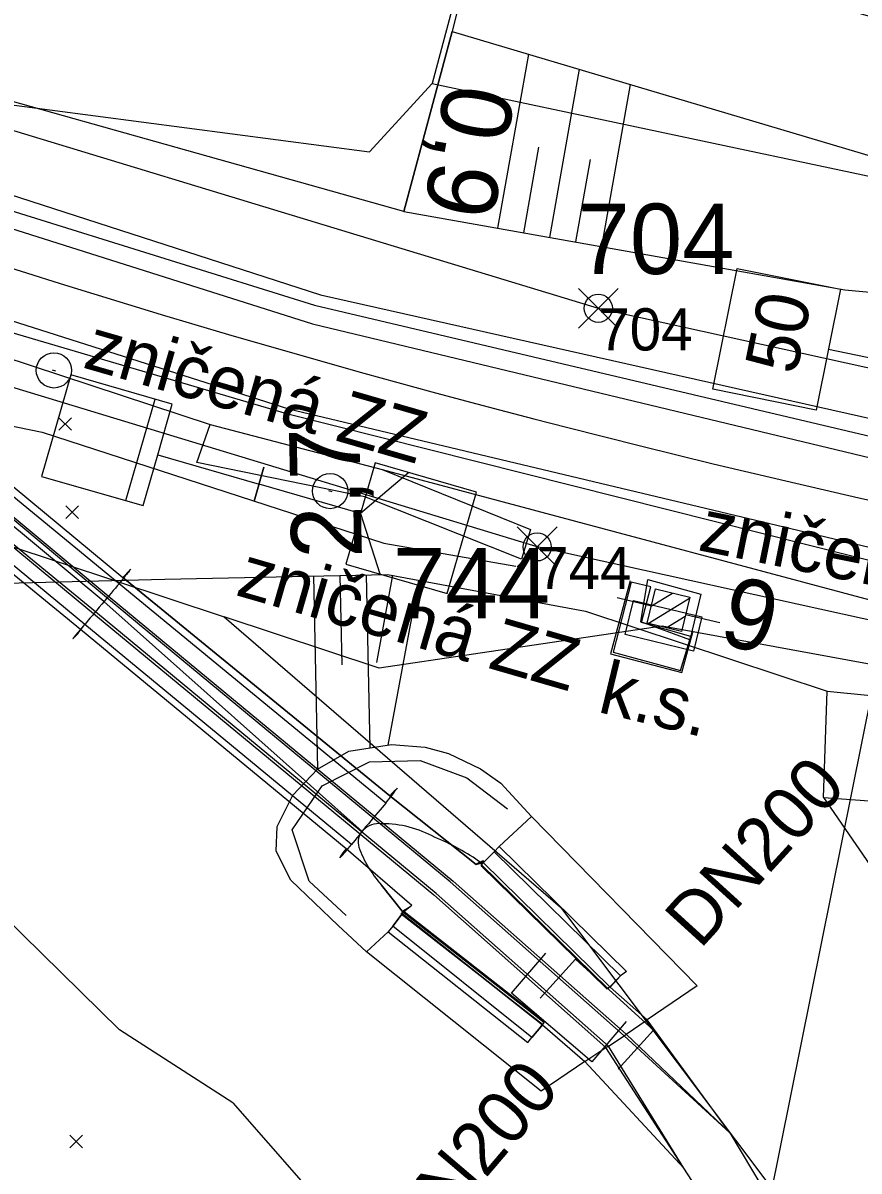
# Model space of a CAD drawing. Extents: x -800194 to -799078, y -1007177 to -1006597.
# Drawn here: x -799739 to -799715.24, y -1007007.87 to -1006975.25 of the extents above; entities that cross this region are included whole.
import ezdxf

# ---------------------------------------------------------------- set-up
doc = ezdxf.new("R2010")
doc.units = 0
for name, color, linetype in [('02_Osa_koleje', 7, 'Continuous'), ('Obvod stavby', 7, 'Continuous'), ('Vrstva 11', 7, 'Continuous'), ('Vrstva 12', 7, 'Continuous'), ('Vrstva 16', 7, 'Continuous'), ('Vrstva 17', 7, 'Continuous'), ('Vrstva 18', 7, 'Continuous'), ('Vrstva 23', 7, 'Continuous'), ('Vrstva 25', 7, 'Continuous'), ('Vrstva 4', 7, 'Continuous'), ('Vrstva 43', 7, 'Continuous'), ('Vrstva 48', 7, 'Continuous'), ('Vrstva 49', 7, 'Continuous'), ('Vrstva 5', 7, 'Continuous'), ('Vrstva 50', 7, 'Continuous'), ('Vrstva 55', 7, 'Continuous'), ('Vrstva 60', 7, 'Continuous'), ('Vrstva 7', 7, 'Continuous')]:
    doc.layers.add(name, color=color, linetype=linetype)

msp = doc.modelspace()

# ---------------------------------------------------------------- linework, layer by layer
at = {"layer": '02_Osa_koleje'}
msp.add_lwpolyline([(-799739.853, -1006982.055), (-799738.9, -1006982.357), (-799737.946, -1006982.656), (-799736.991, -1006982.951), (-799736.034, -1006983.244), (-799735.077, -1006983.533), (-799734.119, -1006983.819), (-799733.16, -1006984.102), (-799732.199, -1006984.381), (-799731.238, -1006984.657), (-799730.276, -1006984.93), (-799729.313, -1006985.2), (-799728.35, -1006985.467), (-799727.385, -1006985.73), (-799726.419, -1006985.989), (-799725.453, -1006986.246), (-799724.485, -1006986.499), (-799723.517, -1006986.749)], dxfattribs=at)
msp.add_arc((-799651.022, -1006703.891), 292, 255.62486, 308.20516, dxfattribs=at)
at = {"layer": 'Obvod stavby'}
for p, q in [((-799723.214, -1006983.924), (-799722.082, -1006982.793)), ((-799723.214, -1006982.793), (-799722.082, -1006983.924)), ((-799724.952, -1006990.705), (-799723.82, -1006989.574)), ((-799724.952, -1006989.574), (-799723.82, -1006990.705))]:
    msp.add_line(p, q, dxfattribs=at)
msp.add_lwpolyline([(-799664.426, -1006999.087), (-799684.601, -1006997.477), (-799704.619, -1006994.49), (-799724.386, -1006990.14), (-799749.554, -1006982.491), (-799772.102, -1006973.528), (-799780.707, -1006969.551), (-799777.674, -1006963.242), (-799769.263, -1006967.129), (-799747.228, -1006975.889), (-799722.648, -1006983.359), (-799703.35, -1006987.606), (-799683.806, -1006990.523), (-799664.228, -1006992.091)], dxfattribs=at)
for centre in [(-799722.648, -1006983.359), (-799724.386, -1006990.14)]:
    msp.add_circle(centre, 0.4, dxfattribs=at)
at = {"layer": 'Vrstva 11'}
for p, q in [((-799721.139, -1006991.823), (-799722.111, -1006991.588)), ((-799721.233, -1006992.314), (-799720.055, -1006991.593)), ((-799721.138, -1006991.816), (-799720.542, -1006991.451)), ((-799720.718, -1006992.438), (-799720.18, -1006992.109)), ((-799720.167, -1006992.057), (-799719.195, -1006992.29))]:
    msp.add_line(p, q, dxfattribs=at)
msp.add_lwpolyline([(-799721.022, -1006991.336), (-799720.05, -1006991.57), (-799720.284, -1006992.542), (-799721.256, -1006992.308)], close=True, dxfattribs=at)
at = {"layer": 'Vrstva 12'}
msp.add_lwpolyline([(-799721.236, -1006991.07), (-799719.737, -1006991.48), (-799720.049, -1006992.784), (-799721.435, -1006992.272), (-799721.236, -1006991.07)], dxfattribs=at)
at = {"layer": 'Vrstva 16'}
for p, q in [((-799725.462, -1006998.653), (-799724.55, -1006997.8)), ((-799728.219, -1007000.489), (-799728.813, -1006999.75)), ((-799721.913, -1007004.037), (-799726.857, -1006999.659)), ((-799727.258, -1006999.988), (-799722.361, -1007004.328)), ((-799727.952, -1007000.326), (-799728.231, -1007000.559)), ((-799728.231, -1007000.559), (-799724.23, -1007003.721)), ((-799728.622, -1007001.076), (-799729.241, -1007001.641)), ((-799721.857, -1007003.981), (-799721.255, -1007003.58)), ((-799723.028, -1007004.76), (-799722.434, -1007004.367))]:
    msp.add_line(p, q, dxfattribs=at)
for points in [[(-799726.857, -1006999.659), (-799736.574, -1006991.623), (-799742.439, -1006986.725), (-799754.518, -1006974.879), (-799763.734, -1006965.993), (-799777.293, -1006954.374), (-799779.945, -1006952.099), (-799783.722, -1006948.693)], [(-799783.708, -1006948.669), (-799779.9, -1006952.065), (-799777.252, -1006954.333), (-799763.672, -1006965.935), (-799754.476, -1006974.829), (-799742.393, -1006986.703), (-799736.524, -1006991.578), (-799726.778, -1006999.642)], [(-799784.356, -1006949.5), (-799780.347, -1006952.62), (-799777.716, -1006954.827), (-799764.168, -1006966.436), (-799754.935, -1006975.363), (-799742.857, -1006987.188), (-799736.94, -1006992.081), (-799727.324, -1007000.028)], [(-799727.258, -1006999.988), (-799736.887, -1006992.032), (-799742.859, -1006987.132), (-799754.894, -1006975.337), (-799764.135, -1006966.374), (-799777.698, -1006954.783), (-799780.331, -1006952.581), (-799784.321, -1006949.462)], [(-799779.465, -1006951.506), (-799778.251, -1006952.583), (-799776.738, -1006953.884), (-799763.224, -1006965.504), (-799753.999, -1006974.421), (-799741.964, -1006986.204), (-799736.168, -1006991.012), (-799728.577, -1006997.215), (-799726.123, -1006999.163)], [(-799727.952, -1007000.326), (-799729.82, -1006998.717), (-799737.37, -1006992.486), (-799743.358, -1006987.594), (-799755.401, -1006975.883), (-799764.592, -1006966.926), (-799778.073, -1006955.449), (-799779.598, -1006954.142), (-799780.843, -1006953.125)], [(-799724.268, -1007005.601), (-799729.241, -1007001.641), (-799730.043, -1007000.896), (-799731.391, -1006999.609), (-799731.807, -1006998.789), (-799731.776, -1006998.081), (-799731.332, -1006997.192), (-799730.628, -1006996.451), (-799729.736, -1006995.947), (-799728.528, -1006995.755), (-799727.566, -1006995.827), (-799726.904, -1006996.009), (-799726.001, -1006996.45), (-799725.419, -1006996.855), (-799724.55, -1006997.8), (-799719.837, -1007002.616)], [(-799719.837, -1007002.616), (-799721.255, -1007003.58), (-799722.309, -1007002.649), (-799722.019, -1007002.331), (-799725.605, -1006998.806), (-799725.462, -1006998.653), (-799721.848, -1007002.204), (-799722.019, -1007002.331)], [(-799726.123, -1006999.163), (-799725.923, -1006999.111), (-799725.92, -1006999.107), (-799725.969, -1006999.167)], [(-799725.605, -1006998.806), (-799725.969, -1006999.167), (-799725.978, -1006999.12)], [(-799727.324, -1007000.028), (-799722.434, -1007004.367), (-799722.361, -1007004.328), (-799721.913, -1007004.037), (-799721.857, -1007003.981), (-799726.778, -1006999.642)], [(-799724.23, -1007003.721), (-799724.534, -1007004.077), (-799728.488, -1007000.913), (-799728.199, -1007000.524)], [(-799728.231, -1007000.559), (-799728.25, -1007000.58), (-799728.201, -1007000.516), (-799728.199, -1007000.524), (-799728.219, -1007000.489)], [(-799728.488, -1007000.913), (-799728.622, -1007001.076), (-799724.647, -1007004.218), (-799724.534, -1007004.077)], [(-799724.23, -1007003.721), (-799723.028, -1007004.76), (-799724.268, -1007005.601)]]:
    msp.add_lwpolyline(points, dxfattribs=at)
for centre, major_axis, ratio, start_param, end_param in [((-799728.904, -1006998.513), (-0.566, -0.095), 0.888473, 4.396597, 6.415472), ((-799729.06, -1007000.766), (-2.796, -1.224), 0.88479, 3.718308, 4.259024), ((-799730.273, -1007003.369), (-6.212, -1.397), 0.847151, 3.77745, 4.035936), ((-799725.41, -1006997.773), (-4.211, 0.231), 0.818659, 0.330695, 0.676051), ((-799727.773, -1007000.273), (1.862, 1.216), 0.026669, 5.99696, 6.747447), ((-799726.195, -1006999.167), (-2.024, -1.323), 0.007629, 6.252324, 6.798297)]:
    msp.add_ellipse(centre, major_axis=major_axis, ratio=ratio, start_param=start_param, end_param=end_param, dxfattribs=at)
at = {"layer": 'Vrstva 17'}
for points in [[(-799726.806, -1006975.491), (-799728.174, -1006980.607), (-799746.39, -1006975.498), (-799745.242, -1006970.318), (-799744.263, -1006965.815), (-799756.721, -1006963.941)], [(-799695.807, -1006967.611), (-799698.37, -1006979.283), (-799711.621, -1006976.014), (-799725.913, -1006971.918), (-799726.806, -1006975.491)], [(-799746.564, -1006986.717), (-799745.074, -1006985.521), (-799738.458, -1006986.883), (-799728.745, -1006990.03), (-799724.988, -1006990.685)], [(-799721.747, -1006991.106), (-799722.3, -1006993.177), (-799720.272, -1006993.705), (-799719.96, -1006992.563)], [(-799729.82, -1007000.617), (-799730.868, -1006999.634), (-799731.355, -1006998.181), (-799730.498, -1006996.925), (-799729.155, -1006996.246), (-799727.711, -1006996.213), (-799726.389, -1006996.698), (-799725.227, -1006997.578)]]:
    msp.add_lwpolyline(points, dxfattribs=at)
at = {"layer": 'Vrstva 18'}
for p, q in [((-799728.577, -1006997.215), (-799736.168, -1006991.012)), ((-799729.364, -1006998.225), (-799736.701, -1006991.694)), ((-799729.82, -1006998.717), (-799737.37, -1006992.486)), ((-799726.123, -1006999.163), (-799728.577, -1006997.215)), ((-799727.952, -1007000.326), (-799729.82, -1006998.717)), ((-799722.019, -1007002.331), (-799725.605, -1006998.806)), ((-799725.98, -1006999.167), (-799722.374, -1007002.692)), ((-799722.407, -1007002.695), (-799725.98, -1006999.2)), ((-799728.813, -1006999.75), (-799728.219, -1007000.489)), ((-799728.199, -1007000.524), (-799728.488, -1007000.913)), ((-799724.238, -1007003.715), (-799728.25, -1007000.58)), ((-799724.23, -1007003.721), (-799728.231, -1007000.559)), ((-799728.199, -1007000.524), (-799728.201, -1007000.516)), ((-799724.197, -1007003.62), (-799728.169, -1007000.506)), ((-799728.168, -1007000.512), (-799724.201, -1007003.621)), ((-799724.534, -1007004.077), (-799728.488, -1007000.913)), ((-799722.374, -1007002.692), (-799722.372, -1007002.691))]:
    msp.add_line(p, q, dxfattribs=at)
for points in [[(-799776.738, -1006953.884), (-799763.224, -1006965.504), (-799753.999, -1006974.421), (-799741.964, -1006986.204), (-799736.168, -1006991.012)], [(-799728.689, -1006997.417), (-799736.272, -1006991.186), (-799742.111, -1006986.385), (-799754.178, -1006974.631), (-799763.368, -1006965.72), (-799777.061, -1006954.31)], [(-799736.701, -1006991.694), (-799742.573, -1006986.82), (-799754.68, -1006975.182), (-799763.887, -1006966.256), (-799777.391, -1006954.732)], [(-799729.664, -1006998.596), (-799737.245, -1006992.341), (-799743.186, -1006987.438), (-799755.222, -1006975.72), (-799764.444, -1006966.802), (-799777.959, -1006955.323)], [(-799737.37, -1006992.486), (-799743.358, -1006987.594), (-799755.401, -1006975.883), (-799764.592, -1006966.926), (-799778.073, -1006955.449)], [(-799725.98, -1006999.167), (-799725.92, -1006999.107), (-799725.923, -1006999.111), (-799722.309, -1007002.649)], [(-799725.605, -1006998.806), (-799725.969, -1006999.167), (-799725.968, -1006999.201), (-799722.404, -1007002.693)], [(-799725.969, -1006999.167), (-799725.98, -1006999.167), (-799725.98, -1006999.2), (-799725.968, -1006999.201)], [(-799728.201, -1007000.516), (-799728.25, -1007000.58), (-799728.231, -1007000.559)], [(-799724.194, -1007003.649), (-799728.201, -1007000.516), (-799728.169, -1007000.506)], [(-799728.169, -1007000.506), (-799728.168, -1007000.512), (-799728.199, -1007000.524)], [(-799722.309, -1007002.649), (-799722.321, -1007002.641), (-799722.374, -1007002.692), (-799722.407, -1007002.695), (-799722.404, -1007002.693), (-799722.372, -1007002.691), (-799722.019, -1007002.331), (-799722.309, -1007002.649)], [(-799724.201, -1007003.621), (-799724.197, -1007003.656), (-799724.534, -1007004.077), (-799724.23, -1007003.721)], [(-799724.194, -1007003.649), (-799724.238, -1007003.715), (-799724.23, -1007003.721)], [(-799724.197, -1007003.656), (-799724.194, -1007003.649), (-799724.197, -1007003.62), (-799724.201, -1007003.621)]]:
    msp.add_lwpolyline(points, dxfattribs=at)
for centre, major_axis, ratio, start_param, end_param in [((-799736.897, -1006992.163), (-0.963, -1.369), 0.041864, 3.408659, 3.947328), ((-799737.23, -1006992.158), (1.296, 1.385), 0.007101, 5.99726, 6.885866), ((-799736.745, -1006991.75), (0.647, 0.768), 0.002373, 0.747313, 2.45121), ((-799736.371, -1006991.391), (-1.212, -1.352), 0.012722, 5.667277, 6.576621), ((-799736.715, -1006991.366), (0.854, 1.349), 0.064947, 3.376238, 3.945747), ((-799729.601, -1006998.375), (1.227, 1.391), 0.038982, 5.50568, 5.9942), ((-799729.675, -1006998.422), (1.311, 1.425), 0.009263, 6.006131, 6.851805), ((-799729.164, -1006998.01), (-0.65, -0.786), 0.017237, 3.872792, 5.567675), ((-799728.904, -1006998.513), (-0.566, -0.095), 0.888473, 4.396597, 6.415472), ((-799729.06, -1007000.766), (2.796, 1.224), 0.88479, 0.576715, 1.117431), ((-799730.273, -1007003.369), (-6.212, -1.397), 0.847151, 3.77745, 4.035936), ((-799728.754, -1006997.452), (-1.245, -1.521), 0.021997, 5.712311, 6.543003), ((-799728.95, -1006997.634), (-1.036, -1.326), 0.024932, 0.238319, 0.779035), ((-799725.41, -1006997.773), (-4.211, 0.231), 0.818659, 0.330695, 0.676051), ((-799727.773, -1007000.273), (1.862, 1.216), 0.026669, 5.99696, 6.747447), ((-799726.195, -1006999.167), (-2.024, -1.323), 0.007629, 6.252324, 6.798297)]:
    msp.add_ellipse(centre, major_axis=major_axis, ratio=ratio, start_param=start_param, end_param=end_param, dxfattribs=at)
at = {"layer": 'Vrstva 23'}
msp.add_lwpolyline([(-799721.159, -1006991.27), (-799721.712, -1006991.14), (-799722.223, -1006993.135), (-799720.312, -1006993.651), (-799720.015, -1006992.683), (-799721.422, -1006992.285), (-799721.159, -1006991.27)], dxfattribs=at)
at = {"layer": 'Vrstva 25'}
msp.add_lwpolyline([(-799721.886, -1006992.632), (-799721.652, -1006991.66), (-799719.708, -1006992.128), (-799719.942, -1006993.1), (-799721.886, -1006992.632)], dxfattribs=at)
at = {"layer": 'Vrstva 4'}
for points in [[(-799766.319, -1006970.565), (-799760.949, -1006972.542), (-799747.638, -1006977.46), (-799730.549, -1006982.982), (-799710.066, -1006987.578), (-799704.728, -1006988.346), (-799693.001, -1006990.373), (-799682.434, -1006991.64), (-799671.27, -1006992.619), (-799659.31, -1006993.026), (-799648.69, -1006993.125), (-799637.398, -1006992.704), (-799625.913, -1006992.175), (-799614.965, -1006990.831), (-799603.911, -1006989.312), (-799592.728, -1006987.172), (-799581.605, -1006984.547), (-799570.583, -1006981.598), (-799559.909, -1006978.216), (-799542.956, -1006972.25), (-799531.79, -1006967.658), (-799521.285, -1006962.191), (-799511.236, -1006957.129)], [(-799779.678, -1006964.304), (-799766.319, -1006970.565), (-799761.253, -1006973.176), (-799747.77, -1006978.421), (-799730.774, -1006983.8), (-799710.333, -1006988.709), (-799704.916, -1006989.741), (-799693.131, -1006991.407), (-799682.585, -1006992.929), (-799671.325, -1006993.879), (-799659.363, -1006994.45), (-799648.66, -1006994.501), (-799637.23, -1006994.127), (-799626.066, -1006993.335), (-799614.788, -1006992.17), (-799603.669, -1006990.506), (-799592.467, -1006988.452), (-799581.281, -1006985.916), (-799570.22, -1006982.998), (-799559.296, -1006979.606), (-799542.375, -1006973.485), (-799531.236, -1006968.774), (-799520.48, -1006963.762), (-799510.394, -1006958.536)], [(-799776.864, -1006969.085), (-799770.965, -1006971.646), (-799761.91, -1006975.649), (-799748.544, -1006980.777), (-799731.457, -1006986.215), (-799711.132, -1006991.054), (-799705.482, -1006992.16), (-799693.53, -1006994.084), (-799682.801, -1006995.384), (-799671.514, -1006996.319), (-799659.449, -1006996.851), (-799648.588, -1006996.949), (-799637.262, -1006996.573), (-799625.835, -1006995.773), (-799614.546, -1006994.586), (-799603.199, -1006992.945), (-799591.969, -1006990.857), (-799580.647, -1006988.335), (-799569.534, -1006985.311), (-799558.557, -1006981.947), (-799541.405, -1006975.739), (-799530.263, -1006971.071), (-799519.455, -1006966), (-799509.248, -1006960.724)], [(-799776.864, -1006969.085), (-799771.262, -1006971.982), (-799762.131, -1006976.093), (-799748.706, -1006981.286), (-799731.51, -1006986.353), (-799711.222, -1006991.459), (-799705.527, -1006992.587), (-799693.582, -1006994.543), (-799682.85, -1006995.904), (-799671.5, -1006996.805), (-799659.556, -1006997.356), (-799648.616, -1006997.341), (-799637.276, -1006997.071), (-799625.828, -1006996.297), (-799614.43, -1006995.109), (-799603.18, -1006993.475), (-799591.849, -1006991.264), (-799580.564, -1006988.698), (-799569.449, -1006985.746), (-799558.385, -1006982.386), (-799541.268, -1006976.227), (-799530.102, -1006971.505), (-799519.398, -1006966.36), (-799509.087, -1006961.127)], [(-799779.011, -1006963.023), (-799770.632, -1006967.944), (-799766.319, -1006970.565), (-799761.021, -1006972.82), (-799747.748, -1006977.966), (-799730.719, -1006983.271), (-799710.195, -1006988.108), (-799704.765, -1006989.181), (-799693.072, -1006990.965), (-799682.554, -1006992.238), (-799671.266, -1006993.222), (-799659.388, -1006993.765), (-799648.658, -1006993.824), (-799637.385, -1006993.531), (-799625.769, -1006992.728), (-799614.9, -1006991.542), (-799603.91, -1006989.963), (-799592.572, -1006987.892), (-799581.421, -1006985.419), (-799570.327, -1006982.332), (-799559.429, -1006979.066), (-799542.601, -1006973.013), (-799531.454, -1006968.25), (-799520.744, -1006963.214)], [(-799776.864, -1006969.085), (-799771.693, -1006972.522), (-799762.217, -1006976.394), (-799748.898, -1006981.647), (-799733.68, -1006986.66), (-799728.795, -1006987.945), (-799711.349, -1006992.599), (-799705.744, -1006994.116), (-799693.689, -1006996.09), (-799689.347, -1006996.226), (-799688.222, -1006996.296), (-799683.105, -1006997.407), (-799671.667, -1006998.275)], [(-799734.064, -1006987.737), (-799733.68, -1006986.66), (-799728.795, -1006987.945), (-799724.58, -1006989.646), (-799724.833, -1006990.487), (-799729.281, -1006988.715), (-799734.064, -1006987.737)]]:
    msp.add_lwpolyline(points, dxfattribs=at)
at = {"layer": 'Vrstva 43'}
for points in [[(-799721.858, -1007003.626), (-799722.831, -1007004.768), (-799725.115, -1007002.822), (-799724.142, -1007001.68)], [(-799724.303, -1007002.961), (-799723.293, -1007001.851), (-799721.075, -1007003.871), (-799722.084, -1007004.98)]]:
    msp.add_lwpolyline(points, dxfattribs=at)
at = {"layer": 'Vrstva 48'}
for p, q in [((-799725.506, -1006981.082), (-799724.627, -1006976.139)), ((-799724.029, -1006981.344), (-799723.18, -1006976.569)), ((-799722.552, -1006981.607), (-799721.733, -1006977)), ((-799724.767, -1006981.213), (-799724.335, -1006978.784)), ((-799723.291, -1006981.476), (-799722.873, -1006979.13)), ((-799729.993, -1006990.948), (-799729.94, -1006993.49)), ((-799729.243, -1006990.933), (-799729.14, -1006995.852)), ((-799728.495, -1006990.947), (-799728.955, -1006993.422)), ((-799730.742, -1006990.964), (-799730.628, -1006996.451)), ((-799727.758, -1006991.084), (-799728.628, -1006995.771))]:
    msp.add_line(p, q, dxfattribs=at)
at = {"layer": 'Vrstva 49'}
for p, q in [((-799737.98, -1006986.471), (-799737.626, -1006986.825)), ((-799737.98, -1006986.825), (-799737.626, -1006986.471)), ((-799737.782, -1006988.977), (-799737.428, -1006989.331)), ((-799737.782, -1006989.331), (-799737.428, -1006988.977)), ((-799716.248, -1006997.261), (-799716.141, -1006994.243)), ((-799718.907, -1007006.786), (-799721.255, -1007003.58)), ((-799718.907, -1007006.786), (-799721.857, -1007003.981)), ((-799722.361, -1007004.328), (-799722.434, -1007004.367)), ((-799720.214, -1007007.792), (-799722.361, -1007004.328)), ((-799720.214, -1007007.792), (-799722.434, -1007004.367)), ((-799720.214, -1007007.792), (-799723.028, -1007004.76)), ((-799737.668, -1007006.857), (-799737.314, -1007007.211)), ((-799737.668, -1007007.211), (-799737.314, -1007006.857))]:
    msp.add_line(p, q, dxfattribs=at)
for points in [[(-799728.174, -1006980.607), (-799726.806, -1006975.491), (-799714.47, -1006979.159), (-799704.928, -1006981.248), (-799699.097, -1006983.466), (-799688.779, -1006985.763), (-799678.423, -1006987.219), (-799669.363, -1006989.921)], [(-799728.174, -1006980.607), (-799715.637, -1006982.837), (-799705.851, -1006983.743), (-799700.586, -1006985.508), (-799691.67, -1006987.253), (-799678.693, -1006988.601), (-799669.363, -1006989.921)], [(-799733.039, -1007005.939), (-799736.26, -1007003.86), (-799742.34, -1006997.896), (-799743.342, -1006994.901), (-799739.871, -1006991.182), (-799734.968, -1006991.052), (-799728.642, -1006990.92), (-799723.01, -1006991.966), (-799716.141, -1006994.243), (-799710.319, -1006994.817)], [(-799723.028, -1007004.76), (-799724.268, -1007005.601), (-799729.241, -1007001.641), (-799730.043, -1007000.896), (-799731.391, -1006999.609), (-799731.807, -1006998.789), (-799731.776, -1006998.081), (-799731.332, -1006997.192), (-799730.628, -1006996.451), (-799729.736, -1006995.947), (-799728.528, -1006995.755), (-799727.566, -1006995.827), (-799726.904, -1006996.009), (-799726.001, -1006996.45), (-799725.419, -1006996.855), (-799724.55, -1006997.8), (-799719.837, -1007002.616), (-799721.255, -1007003.58)], [(-799716.248, -1006997.261), (-799711.439, -1007004.242), (-799711.113, -1007006.25), (-799707.442, -1007011.019), (-799702.585, -1007019.595), (-799698.243, -1007027.001), (-799684.872, -1007037.347), (-799668.902, -1007051.666)], [(-799716.248, -1006997.261), (-799713.515, -1006997.457), (-799709.895, -1006999.809), (-799706.577, -1006999.538), (-799702.816, -1006999.606), (-799701.051, -1007000.939), (-799691.907, -1007002.76), (-799679.882, -1007005.3), (-799670.416, -1007005.115), (-799649.119, -1007006.099), (-799641.812, -1007006.94)], [(-799718.907, -1007006.786), (-799721.913, -1007004.037), (-799721.857, -1007003.981)], [(-799733.039, -1007005.939), (-799730.086, -1007009.294), (-799720.161, -1007021.94)], [(-799718.907, -1007006.786), (-799714.515, -1007014.16), (-799704.214, -1007027.237), (-799692.017, -1007040.081), (-799674.887, -1007054.948)], [(-799676.078, -1007055.763), (-799692.866, -1007041.408), (-799705.479, -1007027.95), (-799715.681, -1007014.777), (-799720.214, -1007007.792)]]:
    msp.add_lwpolyline(points, dxfattribs=at)
at = {"layer": 'Vrstva 5'}
for p, q in [((-799713.166, -1006985.129), (-799716.107, -1006984.535)), ((-799720.48, -1007022.094), (-799714.568, -1006992.803))]:
    msp.add_line(p, q, dxfattribs=at)
msp.add_lwpolyline([(-799715.76, -1006982.82), (-799716.453, -1006986.251), (-799719.394, -1006985.657), (-799718.701, -1006982.227)], close=True, dxfattribs=at)
at = {"layer": 'Vrstva 50'}
for p, q in [((-799738.172, -1006985.111), (-799738.076, -1006985.139)), ((-799730.319, -1006988.54), (-799730.223, -1006988.568))]:
    msp.add_line(p, q, dxfattribs=at)
for centre in [(-799738.124, -1006985.125), (-799730.271, -1006988.554)]:
    msp.add_circle(centre, 0.5, dxfattribs=at)
at = {"layer": 'Vrstva 55'}
msp.add_line((-799727.37, -1006976.97), (-799691.32, -1006984.61), dxfattribs=at)
for points in [[(-799785.23, -1006937.71), (-799791.69, -1006959.99), (-799791.97, -1006960.97), (-799746.76, -1006987.67), (-799745.68, -1006988.03), (-799733.28, -1006992.13)], [(-799741.57, -1006968.68), (-799738.19, -1006957.26), (-799723.4, -1006962.09), (-799727.37, -1006976.97)], [(-799741.57, -1006968.68), (-799744.25, -1006976.52), (-799740.85, -1006977.38), (-799729.15, -1006978.91), (-799727.37, -1006976.97)], [(-799667.22, -1007009.16), (-799678.94, -1007000.07), (-799720.83, -1006992.39), (-799728.88, -1006993.59), (-799733.28, -1006992.13)], [(-799733.28, -1006992.13), (-799723.72, -1007000.38), (-799700.54, -1007031.23)]]:
    msp.add_lwpolyline(points, dxfattribs=at)
at = {"layer": 'Vrstva 60'}
for p, q in [((-799722.648, -1006983.359), (-799722.648, -1006983.359)), ((-799724.386, -1006990.14), (-799724.386, -1006990.14))]:
    msp.add_line(p, q, dxfattribs=at)
at = {"layer": 'Vrstva 7'}
for p, q in [((-799736.08, -1006988.826), (-799735.248, -1006985.944)), ((-799735.174, -1006987.526), (-799732.292, -1006988.358)), ((-799732.153, -1006987.878), (-799732.431, -1006988.838)), ((-799732.431, -1006988.838), (-799732.153, -1006987.878)), ((-799729.41, -1006989.19), (-799732.292, -1006988.358))]:
    msp.add_line(p, q, dxfattribs=at)
for points in [[(-799735.174, -1006987.526), (-799734.758, -1006986.085), (-799737.641, -1006985.253), (-799738.473, -1006988.136), (-799735.59, -1006988.967), (-799735.174, -1006987.526)], [(-799729.41, -1006989.19), (-799729.826, -1006990.631), (-799726.943, -1006991.463), (-799726.111, -1006988.58), (-799728.994, -1006987.749), (-799729.41, -1006989.19)], [(-799728.031, -1006988.026), (-799729.41, -1006989.19), (-799728.863, -1006990.909)]]:
    msp.add_lwpolyline(points, dxfattribs=at)

# ---------------------------------------------------------------- texts
at = {"layer": 'Obvod stavby'}
for s, p in [('704', (-799723.238, -1006982.386)), ('744', (-799728.485, -1006992.174))]:
    msp.add_text(s, height=2, rotation=360, dxfattribs=at).set_placement(p)
at = {"layer": 'Vrstva 11'}
msp.add_text('9', height=2, rotation=346.4607, dxfattribs=at).set_placement((-799719.279, -1006992.868))
at = {"layer": 'Vrstva 25'}
msp.add_text('k.s.', height=1.5, rotation=346.4607, dxfattribs=at).set_placement((-799722.701, -1006994.822))
at = {"layer": 'Vrstva 43'}
for rotation, p in [(47.695, (-799719.754, -1007001.594)), (49.5752, (-799727.74, -1007010.31))]:
    msp.add_text('DN200', height=1.5, rotation=rotation, dxfattribs=at).set_placement(p)
at = {"layer": 'Vrstva 48'}
for s, rotation, p in [('0,9', 259.9141, (-799726.972, -1006976.905)), ('2,7', 91.1954, (-799729.366, -1006990.445))]:
    msp.add_text(s, height=2, rotation=rotation, dxfattribs=at).set_placement(p)
at = {"layer": 'Vrstva 5'}
msp.add_text('50', height=1.5, rotation=78.5895, dxfattribs=at).set_placement((-799717.023, -1006985.282))
at = {"layer": 'Vrstva 50'}
for rotation, p in [(343.903, (-799737.339, -1006985.034)), (348.5895, (-799719.846, -1006990.228)), (343.903, (-799732.994, -1006991.5))]:
    msp.add_text('zničená ZZ', height=1.5, rotation=rotation, dxfattribs=at).set_placement(p)
at = {"layer": 'Vrstva 60'}
for s, p in [('704', (-799722.648, -1006984.559)), ('744', (-799724.386, -1006991.34))]:
    msp.add_text(s, height=1.2, dxfattribs=at).set_placement(p)

doc.saveas('drawing.dxf')
